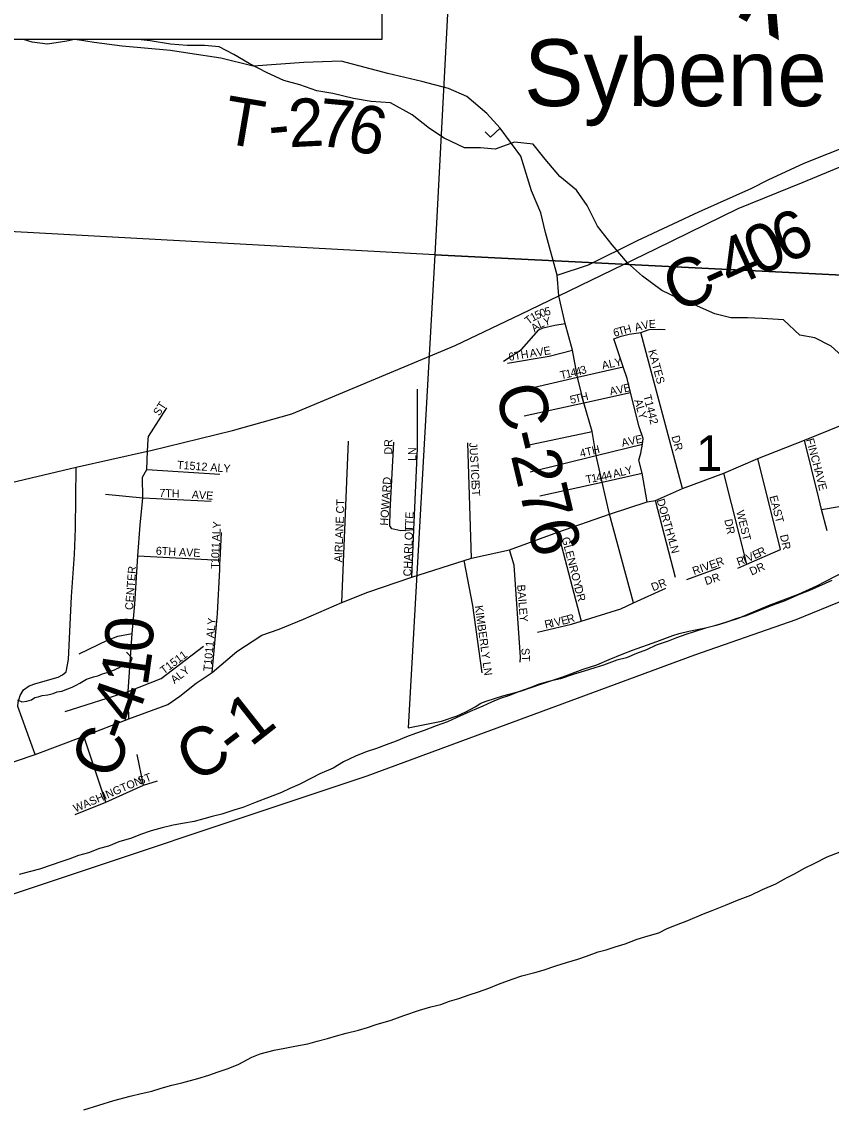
# Model space of a CAD drawing. Extents: x 0 to 34, y 0 to 22.
# Drawn here: x 7.417 to 8.374, y 14.797 to 16.08 of the extents above; entities that cross this region are included whole.
import ezdxf

# ---------------------------------------------------------------- set-up
doc = ezdxf.new("R2010")
doc.units = 0
for name, color, linetype in [('GM_X_County', 7, 'Continuous'), ('GM_X_County_Road', 7, 'Continuous'), ('GM_X_County_Road_Text', 7, 'Continuous'), ('GM_X_Major_River', 7, 'Continuous'), ('GM_X_Minor_River', 7, 'Continuous'), ('GM_X_Minor_River_Text', 7, 'Continuous'), ('GM_X_Section', 7, 'Continuous'), ('GM_X_Section_Text', 7, 'Continuous'), ('GM_X_Township', 7, 'Continuous'), ('GM_X_Township_Road', 7, 'Continuous'), ('GM_X_Township_Road_Text', 7, 'Continuous'), ('GM_X_Township_ROW', 7, 'Continuous'), ('GM_X_Township_Subdivision', 7, 'Continuous'), ('GM_X_Township_Subdivision_Text', 7, 'Continuous'), ('GM_X_Unincorporated_Text', 7, 'Continuous'), ('GM_X_US_Route', 7, 'Continuous'), ('SH_Text', 7, 'Continuous')]:
    doc.layers.add(name, color=color, linetype=linetype)

msp = doc.modelspace()

# ---------------------------------------------------------------- linework, layer by layer
at = {"layer": 'GM_X_County'}
msp.add_lwpolyline([(5.8119, 14.8141), (6.1284, 14.8081), (6.2942, 14.8107), (6.3434, 14.8225), (6.4918, 14.8467), (6.6258, 14.8615), (6.8567, 14.9043), (7.3029, 15.0101), (7.3665, 15.0352), (7.8253, 15.188), (8.2132, 15.3314), (8.3328, 15.3731), (8.5648, 15.4679), (8.676, 15.5284), (8.7195, 15.5558), (8.7393, 15.5616), (8.7787, 15.5707), (8.8056, 15.586), (8.8602, 15.6149), (8.8974, 15.6271), (8.9084, 15.63)], dxfattribs=at)
at = {"layer": 'GM_X_County_Road'}
for points in [[(8.0503, 15.7803), (8.0874, 15.7928), (8.1452, 15.8216), (8.2179, 15.8552), (8.2805, 15.8833), (8.2998, 15.8934), (8.3423, 15.9128), (8.3998, 15.9358), (8.4361, 15.9518), (8.467, 15.9639)], [(8.112, 15.4978), (8.1034, 15.5357), (8.0964, 15.5671), (8.0914, 15.5955), (8.0818, 15.6296), (8.0743, 15.6597), (8.0684, 15.6919), (8.0596, 15.7232), (8.0522, 15.7561)], [(7.2824, 15.1625), (7.4327, 15.2135), (7.4902, 15.235), (7.5435, 15.2556), (7.5896, 15.2726), (7.604, 15.2823), (7.6232, 15.2976), (7.6422, 15.3104), (7.6712, 15.3351), (7.701, 15.3545), (7.7215, 15.3617), (7.7503, 15.3736), (7.7956, 15.3933), (7.8261, 15.4054), (7.8781, 15.423), (7.9403, 15.4429), (7.949, 15.4456), (7.9939, 15.4554), (8.0511, 15.4763), (8.112, 15.4978), (8.1567, 15.5122), (8.1664, 15.5139), (8.1986, 15.5279), (8.2473, 15.5462), (8.2875, 15.5635), (8.3426, 15.5854), (8.3864, 15.6029)], [(7.4327, 15.2135), (7.4124, 15.2702), (7.4127, 15.2754), (7.4148, 15.283), (7.4189, 15.2899), (7.4258, 15.2944), (7.4334, 15.2972), (7.4601, 15.3049), (7.4652, 15.3075), (7.4693, 15.3113), (7.4722, 15.3256), (7.4756, 15.4004), (7.4791, 15.4499), (7.4805, 15.4807), (7.4811, 15.5532)]]:
    msp.add_lwpolyline(points, dxfattribs=at)
at = {"layer": 'GM_X_Major_River'}
for points in [[(8.375, 15.4192), (8.3592, 15.412), (8.3486, 15.4075), (8.3365, 15.4025), (8.3187, 15.3949), (8.3085, 15.3912), (8.2964, 15.3866), (8.2835, 15.3813), (8.2726, 15.3771), (8.2627, 15.3741), (8.2487, 15.3692), (8.2381, 15.3658), (8.2257, 15.3627), (8.2124, 15.3586), (8.2022, 15.3552), (8.1913, 15.3514), (8.1814, 15.3476), (8.1674, 15.3427), (8.1557, 15.3373), (8.144, 15.3328), (8.1323, 15.3279), (8.1209, 15.3248), (8.105, 15.3192), (8.0948, 15.3157), (8.082, 15.312), (8.0702, 15.3085), (8.054, 15.3029), (8.04, 15.2998), (8.0279, 15.296), (8.0177, 15.2923), (8.0056, 15.2877), (7.9927, 15.2828), (7.9829, 15.2794), (7.9727, 15.2752), (7.9621, 15.2707), (7.9473, 15.2642), (7.9307, 15.2566), (7.9205, 15.2521)], [(7.9205, 15.2521), (7.9072, 15.2472), (7.8929, 15.2419), (7.8827, 15.2381), (7.8721, 15.2343), (7.8596, 15.2293), (7.8479, 15.2248), (7.8365, 15.2206), (7.8244, 15.2165), (7.8116, 15.2112), (7.7976, 15.2047), (7.7851, 15.1971), (7.7696, 15.1903), (7.7594, 15.1854), (7.745, 15.1778), (7.734, 15.1733), (7.7242, 15.1683), (7.7087, 15.1626), (7.6943, 15.157), (7.6784, 15.1505), (7.6678, 15.1475), (7.6535, 15.1429), (7.6421, 15.1399), (7.6323, 15.1373), (7.6209, 15.1339), (7.607, 15.1316), (7.596, 15.1297), (7.5831, 15.1267), (7.5699, 15.1229), (7.5574, 15.1187), (7.5468, 15.1145), (7.5317, 15.11), (7.5196, 15.1047), (7.509, 15.102), (7.4958, 15.0971), (7.484, 15.0937), (7.4738, 15.0899), (7.4632, 15.0865), (7.4527, 15.0827), (7.4379, 15.0778), (7.4273, 15.0748), (7.4137, 15.0713)], [(7.4904, 14.793), (7.5082, 14.7986), (7.5259, 14.8039), (7.5452, 14.8089), (7.5581, 14.8123), (7.5709, 14.8149), (7.5819, 14.8187), (7.5944, 14.8221), (7.6061, 14.8248), (7.625, 14.8301), (7.6382, 14.8339), (7.6492, 14.8377), (7.6609, 14.8418), (7.6738, 14.8471), (7.6889, 14.8551), (7.6988, 14.8593), (7.7154, 14.8634), (7.7279, 14.8657), (7.74, 14.8683), (7.7551, 14.871), (7.7661, 14.874), (7.7785, 14.8774), (7.7891, 14.8805), (7.8005, 14.8835), (7.8152, 14.8873), (7.8258, 14.8903), (7.836, 14.8937), (7.8538, 14.899), (7.8689, 14.9047), (7.8875, 14.9108), (7.9007, 14.9146), (7.9124, 14.9176), (7.923, 14.9214), (7.934, 14.9248), (7.9461, 14.929), (7.9571, 14.9324), (7.9695, 14.9369), (7.9809, 14.9418), (7.9971, 14.9475), (8.0085, 14.9513), (8.0236, 14.9555), (8.0338, 14.9581), (8.0486, 14.9634), (8.0614, 14.9672), (8.0747, 14.971), (8.0849, 14.9748), (8.0985, 14.9797), (8.1083, 14.9824), (8.1189, 14.9858), (8.1306, 14.9892), (8.145, 14.9949), (8.1579, 14.9987), (8.1703, 15.0025), (8.1802, 15.0074), (8.1915, 15.0119), (8.2048, 15.0169), (8.2233, 15.0248), (8.2335, 15.0286), (8.2494, 15.035), (8.2634, 15.0411), (8.2793, 15.0468), (8.2929, 15.0536), (8.3088, 15.0604), (8.3216, 15.0676), (8.3315, 15.0726), (8.342, 15.0783), (8.3549, 15.0847), (8.3697, 15.0923), (8.3848, 15.0983)]]:
    msp.add_lwpolyline(points, dxfattribs=at)
at = {"layer": 'GM_X_Minor_River'}
for points in [[(7.4792, 16.0591), (7.4701, 16.0574), (7.4474, 16.0537), (7.4292, 16.056), (7.4188, 16.0591)], [(8.3955, 15.6772), (8.3744, 15.6963), (8.3548, 15.7062), (8.3374, 15.7093), (8.3177, 15.7276), (8.2928, 15.7292), (8.2753, 15.7301), (8.2556, 15.7301), (8.2367, 15.7348), (8.2125, 15.7455), (8.1929, 15.7532), (8.174, 15.7623), (8.1513, 15.7791), (8.1332, 15.7951), (8.1151, 15.8165), (8.0978, 15.8386), (8.0858, 15.8629), (8.073, 15.8812), (8.0534, 15.8972), (8.036, 15.9178), (8.0217, 15.9353), (7.9998, 15.9377), (7.977, 15.9294), (7.9596, 15.931), (7.9407, 15.931), (7.9165, 15.9425), (7.8991, 15.954), (7.8787, 15.97), (7.853, 15.9845), (7.8303, 15.9861), (7.8091, 15.9893), (7.7849, 15.9954), (7.766, 15.9985), (7.7456, 16.0055), (7.7267, 16.0109), (7.707, 16.02), (7.6859, 16.0308), (7.6677, 16.0415), (7.6503, 16.0506), (7.6329, 16.0522), (7.6125, 16.0523), (7.5928, 16.0539), (7.5686, 16.0578), (7.5546, 16.0591)], [(7.4118, 15.2782), (7.417, 15.2755), (7.4227, 15.2765), (7.4284, 15.278), (7.4323, 15.2809), (7.4361, 15.2816), (7.441, 15.2831), (7.4478, 15.2841), (7.4539, 15.2855), (7.4589, 15.2873), (7.4642, 15.2884), (7.4714, 15.2909), (7.4764, 15.2931), (7.4814, 15.2953), (7.4856, 15.2979), (7.4936, 15.3023), (7.5016, 15.3052), (7.5069, 15.3066), (7.5123, 15.3088), (7.518, 15.3102), (7.5218, 15.312), (7.5264, 15.3135), (7.5313, 15.3157), (7.5359, 15.3186), (7.542, 15.3204), (7.5455, 15.3219), (7.5475, 15.3272), (7.5408, 15.3345)]]:
    msp.add_lwpolyline(points, dxfattribs=at)
at = {"layer": 'GM_X_Section'}
for points in [[(6.8391, 16.7743), (6.8455, 16.8788), (7.9583, 16.8099), (7.9053, 15.8044), (6.7831, 15.8661), (6.795, 16.0591)], [(8.9084, 16.7577), (7.9583, 16.8099), (7.9053, 15.8044), (8.9084, 15.7545)], [(8.9084, 15.7545), (7.9053, 15.8044), (7.8739, 15.2448), (7.9133, 15.2527), (7.9318, 15.2591), (7.9421, 15.2637), (7.9531, 15.2697), (7.9599, 15.2739), (7.9663, 15.2765), (7.986, 15.2826), (8.0069, 15.2882), (8.0319, 15.2969), (8.0569, 15.3053), (8.0808, 15.3143), (8.0971, 15.3193), (8.1115, 15.3257), (8.127, 15.3321), (8.1391, 15.3367), (8.168, 15.3469), (8.1869, 15.3541), (8.1945, 15.3563), (8.2059, 15.3593), (8.2256, 15.3631), (8.2365, 15.3658), (8.2536, 15.3711), (8.2646, 15.3745), (8.2775, 15.3801), (8.3002, 15.3896), (8.3355, 15.4032), (8.3574, 15.4127), (8.3893, 15.4293)]]:
    msp.add_lwpolyline(points, dxfattribs=at)
at = {"layer": 'GM_X_Township'}
msp.add_lwpolyline([(5.8119, 14.8141), (6.1284, 14.8081), (6.2942, 14.8107), (6.3434, 14.8225), (6.4918, 14.8467), (6.6258, 14.8615), (6.8567, 14.9043), (7.3029, 15.0101), (7.3665, 15.0352), (7.8253, 15.188), (8.2132, 15.3314), (8.3328, 15.3731), (8.5648, 15.4679), (8.676, 15.5284), (8.7195, 15.5558), (8.7393, 15.5616), (8.7787, 15.5707), (8.8056, 15.586), (8.8602, 15.6149), (8.8974, 15.6271), (8.9084, 15.63)], dxfattribs=at)
at = {"layer": 'GM_X_Township_Road'}
for points in [[(7.6156, 16.0429), (7.5929, 16.0463), (7.5356, 16.0513), (7.5025, 16.0558), (7.4827, 16.059), (7.4826, 16.0591)], [(8.0522, 15.7561), (8.0503, 15.7803), (8.0365, 15.831), (8.031, 15.8543), (8.02, 15.8801), (8.0071, 15.9213), (7.9829, 15.9543), (7.9671, 15.9719), (7.9433, 15.9917), (7.9217, 16.0012), (7.8902, 16.0094), (7.85, 16.0189), (7.7946, 16.0335), (7.7506, 16.0321), (7.6904, 16.0277), (7.6524, 16.0372), (7.6156, 16.0429)], [(8.1403, 15.3927), (8.112, 15.4978)]]:
    msp.add_lwpolyline(points, dxfattribs=at)
at = {"layer": 'GM_X_Township_ROW'}
for points in [[(8.1268, 15.6767), (8.1174, 15.7051)], [(7.8851, 15.5756), (7.8851, 15.6454)], [(8.0132, 15.579), (8.0914, 15.5955)], [(8.1567, 15.5122), (8.1508, 15.5461), (8.1469, 15.5615), (8.149, 15.5697), (8.1511, 15.5806)], [(8.3696, 15.478), (8.363, 15.5031), (8.3595, 15.5165), (8.3591, 15.5182)], [(7.6484, 15.38), (7.651, 15.4323)]]:
    msp.add_lwpolyline(points, dxfattribs=at)
at = {"layer": 'GM_X_Township_Subdivision'}
msp.add_line((7.4823, 16.0591), (7.4827, 16.059), dxfattribs=at)
for points in [[(7.9652, 15.9499), (7.9712, 15.9439), (7.9829, 15.9543)], [(7.9866, 15.6788), (8.0078, 15.6925), (8.0283, 15.7156), (8.0336, 15.7183), (8.0473, 15.7213), (8.0596, 15.7232)], [(8.1174, 15.7051), (8.1259, 15.7082), (8.1355, 15.7106), (8.1493, 15.7128), (8.159, 15.7162), (8.1713, 15.7165), (8.1781, 15.7162)], [(8.1986, 15.5279), (8.1493, 15.7128)], [(7.9915, 15.6764), (8.0407, 15.6848), (8.0684, 15.6919)], [(8.0116, 15.6452), (8.0743, 15.6597), (8.1283, 15.6721)], [(8.1511, 15.5806), (8.1512, 15.5806), (8.1519, 15.5874), (8.1473, 15.601), (8.137, 15.6416), (8.133, 15.6583), (8.1283, 15.6721), (8.1268, 15.6767)], [(8.0111, 15.614), (8.0818, 15.6296), (8.137, 15.6416)], [(7.5664, 15.5859), (7.5666, 15.5895), (7.5884, 15.6236)], [(7.5595, 15.5125), (7.5599, 15.5169), (7.5595, 15.5416), (7.5647, 15.5507), (7.5657, 15.5723), (7.5664, 15.5859)], [(7.7956, 15.3933), (7.8035, 15.5841)], [(7.8807, 15.4792), (7.8652, 15.4781), (7.8545, 15.4804), (7.8522, 15.484), (7.8526, 15.5014), (7.8569, 15.5829)], [(7.949, 15.4456), (7.9447, 15.5821)], [(8.0184, 15.5479), (8.0964, 15.5671), (8.1512, 15.5806)], [(8.3591, 15.5182), (8.3426, 15.5854)], [(7.8781, 15.423), (7.8807, 15.4792), (7.8851, 15.5756)], [(8.3142, 15.4557), (8.2875, 15.5635)], [(7.5647, 15.5507), (7.651, 15.5451)], [(8.0295, 15.5194), (8.1034, 15.5357), (8.1508, 15.5461)], [(8.2745, 15.4384), (8.2473, 15.5462)], [(7.5158, 15.5213), (7.5599, 15.5169), (7.6408, 15.5129)], [(7.5435, 15.2556), (7.5429, 15.2878), (7.5476, 15.3564), (7.5508, 15.3912), (7.5541, 15.4483), (7.5569, 15.4846), (7.5595, 15.5125)], [(8.1902, 15.4226), (8.1664, 15.5139)], [(8.363, 15.5031), (8.3838, 15.5067)], [(8.0511, 15.4763), (8.0787, 15.371)], [(7.651, 15.4323), (7.6513, 15.4394), (7.6515, 15.4432), (7.6533, 15.4759)], [(8.0065, 15.3227), (8.0069, 15.3284), (7.9993, 15.4373), (7.9939, 15.4554)], [(8.2638, 15.4337), (8.2745, 15.4384), (8.3142, 15.4557)], [(7.5541, 15.4483), (7.6515, 15.4432)], [(7.9613, 15.3101), (7.9506, 15.3895), (7.9403, 15.4429)], [(8.2036, 15.4205), (8.2434, 15.4348)], [(8.027, 15.3579), (8.0671, 15.3674), (8.0787, 15.371), (8.1254, 15.3856), (8.1403, 15.3927), (8.1787, 15.4103)], [(7.6422, 15.3104), (7.6482, 15.3753), (7.6484, 15.38)], [(7.4847, 15.3326), (7.5181, 15.3488), (7.5307, 15.3534), (7.5476, 15.3564)], [(7.5429, 15.2878), (7.5819, 15.3033), (7.6319, 15.3415)], [(7.4683, 15.2642), (7.5429, 15.2878)], [(7.5164, 15.1571), (7.4902, 15.235)], [(7.561, 15.1769), (7.5533, 15.2133)], [(7.4802, 15.1423), (7.5164, 15.1571), (7.561, 15.1769), (7.5775, 15.1821)]]:
    msp.add_lwpolyline(points, dxfattribs=at)
at = {"layer": 'GM_X_US_Route'}
for points in [[(8.0072, 15.7345), (8.0522, 15.7561), (8.1668, 15.8115), (8.2644, 15.8594), (8.3413, 15.8906), (8.406, 15.9174), (8.4705, 15.9381), (8.5513, 15.963), (8.6112, 15.9821), (8.6803, 16.0015), (8.8695, 16.0638), (8.9084, 16.0785)], [(6.0693, 15.1798), (6.1716, 15.2129), (6.4895, 15.3107), (6.6363, 15.3535), (6.8543, 15.4074), (6.9758, 15.4387), (7.1396, 15.4749), (7.3278, 15.5172), (7.4811, 15.5532), (7.5657, 15.5723), (7.5697, 15.5732), (7.666, 15.5965), (7.7362, 15.6162), (7.9296, 15.6972), (8.0072, 15.7345)]]:
    msp.add_lwpolyline(points, dxfattribs=at)
at = {"layer": 'SH_Text'}
msp.add_lwpolyline([(6.0532, 16.7743), (7.8426, 16.7743), (7.8426, 16.0591), (6.0532, 16.0591)], close=True, dxfattribs=at)

# ---------------------------------------------------------------- texts
at = {"layer": 'GM_X_County_Road_Text'}
for s, height, rotation, p in [('6', 0.0568, 23.961, (8.3193, 15.7931)), ('0', 0.0568, 24.4887, (8.2876, 15.7787)), ('4', 0.0568, 24.5791, (8.2558, 15.7641)), ('C', 0.0568, 24.6132, (8.1921, 15.735)), ('-', 0.0568, 24.6088, (8.2346, 15.7544)), ('C-276', 0.05682, 283.3713, (7.9766, 15.6456)), ('0', 0.0568, 86.7269, (7.5712, 15.3329)), ('1', 0.0568, 81.6999, (7.5656, 15.2929)), ('4', 0.0568, 70.8715, (7.5514, 15.2484)), ('1', 0.0568, 38.261, (7.6877, 15.2214)), ('-', 0.0568, 70.1263, (7.5432, 15.2257)), ('C', 0.0568, 29.5236, (7.6208, 15.1789)), ('C', 0.0568, 69.9539, (7.5271, 15.1817)), ('-', 0.0568, 37.6716, (7.6687, 15.2068))]:
    msp.add_text(s, height=height, rotation=rotation, dxfattribs=at).set_placement(p)
at = {"layer": 'GM_X_Minor_River_Text'}
msp.add_text('Creek', height=0.09471, rotation=330.2117, dxfattribs=at).set_placement((8.0191, 16.2263))
at = {"layer": 'GM_X_Section_Text'}
msp.add_text('1', height=0.0419, rotation=0, dxfattribs=at).set_placement((8.2144, 15.5489))
at = {"layer": 'GM_X_Township_Road_Text'}
for s, rotation, p in [('T', 350.2894, (7.6525, 15.9373)), ('2', 2.8362, (7.7333, 15.9317)), ('7', 354.6594, (7.7661, 15.9335)), ('6', 345.6826, (7.7986, 15.9306)), ('-', 5.4829, (7.7107, 15.9295))]:
    msp.add_text(s, height=0.0568, rotation=rotation, dxfattribs=at).set_placement(p)
at = {"layer": 'GM_X_Township_Subdivision_Text'}
for s, rotation, p in [('T', 38.0176, (8.0163, 15.7215)), ('1', 27.8778, (8.0212, 15.7254)), ('5', 23.6508, (8.0262, 15.728)), ('0', 21.3491, (8.0315, 15.7303)), ('5', 12.7527, (8.0365, 15.7323)), ('A', 36.6153, (8.0234, 15.7127)), ('L', 24.3131, (8.0296, 15.7174)), ('Y', 14.3901, (8.0353, 15.72)), ('T', 16.4673, (8.1236, 15.7089)), ('H', 14.744, (8.1299, 15.7108)), ('A', 14.4842, (8.1431, 15.7139)), ('V', 12.6367, (8.1511, 15.716)), ('E', 3.2338, (8.1588, 15.7178)), ('6', 16.4619, (8.118, 15.7073)), ('V', 8.5662, (8.0265, 15.6844)), ('E', 9.5171, (8.0349, 15.6857)), ('6TH', 9.0896, (7.9933, 15.679)), ('A', 8.5662, (8.0183, 15.6832)), ('ALY', 11.6897, (8.104, 15.6689)), ('KATES', 285.2564, (8.1578, 15.691)), ('1', 12.3251, (8.0613, 15.6587)), ('4', 12.8053, (8.0671, 15.66)), ('4', 14.8173, (8.0732, 15.6613)), ('3', 15.8508, (8.079, 15.6629)), ('T', 12.3199, (8.0548, 15.6573)), ('AVE', 12.0949, (8.1132, 15.6381)), ('ST', 57.2679, (7.5795, 15.6132)), ('5', 12.7575, (8.0665, 15.6281)), ('T', 12.7637, (8.0722, 15.6294)), ('H', 14.5552, (8.079, 15.631)), ('ALY', 285.9515, (8.1412, 15.6323)), ('T1442', 284.4249, (8.1519, 15.6378)), ('AVE', 12.0949, (8.1273, 15.5773)), ('DR', 90, (7.8551, 15.5681)), ('JUSTICE', 273.242, (7.9462, 15.5823)), ('4TH', 13.4966, (8.0781, 15.5648)), ('DR', 285.516, (8.1853, 15.5894)), ('FINCH', 285.3784, (8.3444, 15.586)), ('LN', 90, (7.8834, 15.5606)), ('T1512 ALY', 355.7947, (7.6003, 15.5515)), ('Y', 13.7363, (8.1319, 15.5442)), ('HOWARD', 86.3656, (7.8501, 15.4839)), ('T', 10.5626, (8.0849, 15.5339)), ('1', 10.566, (8.0915, 15.5351)), ('4', 10.565, (8.0972, 15.5362)), ('4', 13.1759, (8.1034, 15.5373)), ('4', 13.5223, (8.1091, 15.5387)), ('A', 13.7376, (8.1173, 15.5406)), ('L', 13.7371, (8.1254, 15.5426)), ('AVE', 284.0361, (8.3544, 15.5493)), ('7TH', 357.7094, (7.5794, 15.5182)), ('ST', 273.5744, (7.9487, 15.5348)), ('AVE', 355.9142, (7.6178, 15.5165)), ('AIRLANE CT', 87.9032, (7.7959, 15.4406)), ('DORTHY', 286.2191, (8.1677, 15.5144)), ('EAST', 284.8247, (8.3011, 15.5185)), ('WEST', 283.6697, (8.2619, 15.501)), ('Y', 86.9386, (7.6521, 15.4804)), ('CHARLOTTE', 87.9537, (7.8776, 15.4239)), ('DR', 281.8934, (8.2478, 15.4909)), ('L', 86.9482, (7.6518, 15.4737)), ('1', 86.9386, (7.6509, 15.4571)), ('A', 86.9167, (7.6513, 15.4654)), ('GLENROY', 284.8774, (8.0553, 15.4693)), ('LN', 284.7465, (8.1819, 15.466)), ('DR', 282.5337, (8.3136, 15.4726)), ('6TH AVE', 356.9871, (7.5753, 15.4498)), ('0', 87.2512, (7.6503, 15.4454)), ('1', 86.9386, (7.6506, 15.4512)), ('V', 24.6118, (8.2762, 15.4409)), ('E', 24.8965, (8.2838, 15.4444)), ('R', 24.8982, (8.2898, 15.4472)), ('T', 89.8907, (7.6501, 15.433)), ('1', 88.5636, (7.6501, 15.4397)), ('RIVER', 19.748, (8.2121, 15.4256)), ('R', 20.4402, (8.2646, 15.4364)), ('I', 22.5757, (8.272, 15.4392)), ('DR', 23.9607, (8.2802, 15.425)), ('CENTER', 85.7619, (7.5484, 15.384)), ('DR', 18.4332, (8.2264, 15.4136)), ('BAILEY', 274.4864, (8.0028, 15.414)), ('DR', 285.5273, (8.0703, 15.411)), ('DR', 22.3779, (8.1637, 15.4064)), ('KIMBERLY LN', 277.872, (7.9528, 15.3891)), ('T1011 ALY', 84.9571, (7.641, 15.3115)), ('I', 12.8262, (8.0438, 15.364)), ('V', 12.8288, (8.0479, 15.3649)), ('E', 12.8286, (8.056, 15.3667)), ('R', 16.4048, (8.0631, 15.3684)), ('R', 12.8314, (8.0365, 15.3623)), ('T1511', 37.1853, (7.585, 15.3078)), ('ST', 273.5744, (8.0078, 15.339)), ('ALY', 38.0485, (7.5975, 15.2966)), ('WASHINGTON', 23.2784, (7.4803, 15.1447)), ('ST', 20.556, (7.5562, 15.1772))]:
    msp.add_text(s, height=0.00947, rotation=rotation, dxfattribs=at).set_placement(p)
at = {"layer": 'GM_X_Unincorporated_Text'}
msp.add_text('Sybene', height=0.07898, rotation=0, dxfattribs=at).set_placement((8.011, 15.9805))

doc.saveas('drawing.dxf')
